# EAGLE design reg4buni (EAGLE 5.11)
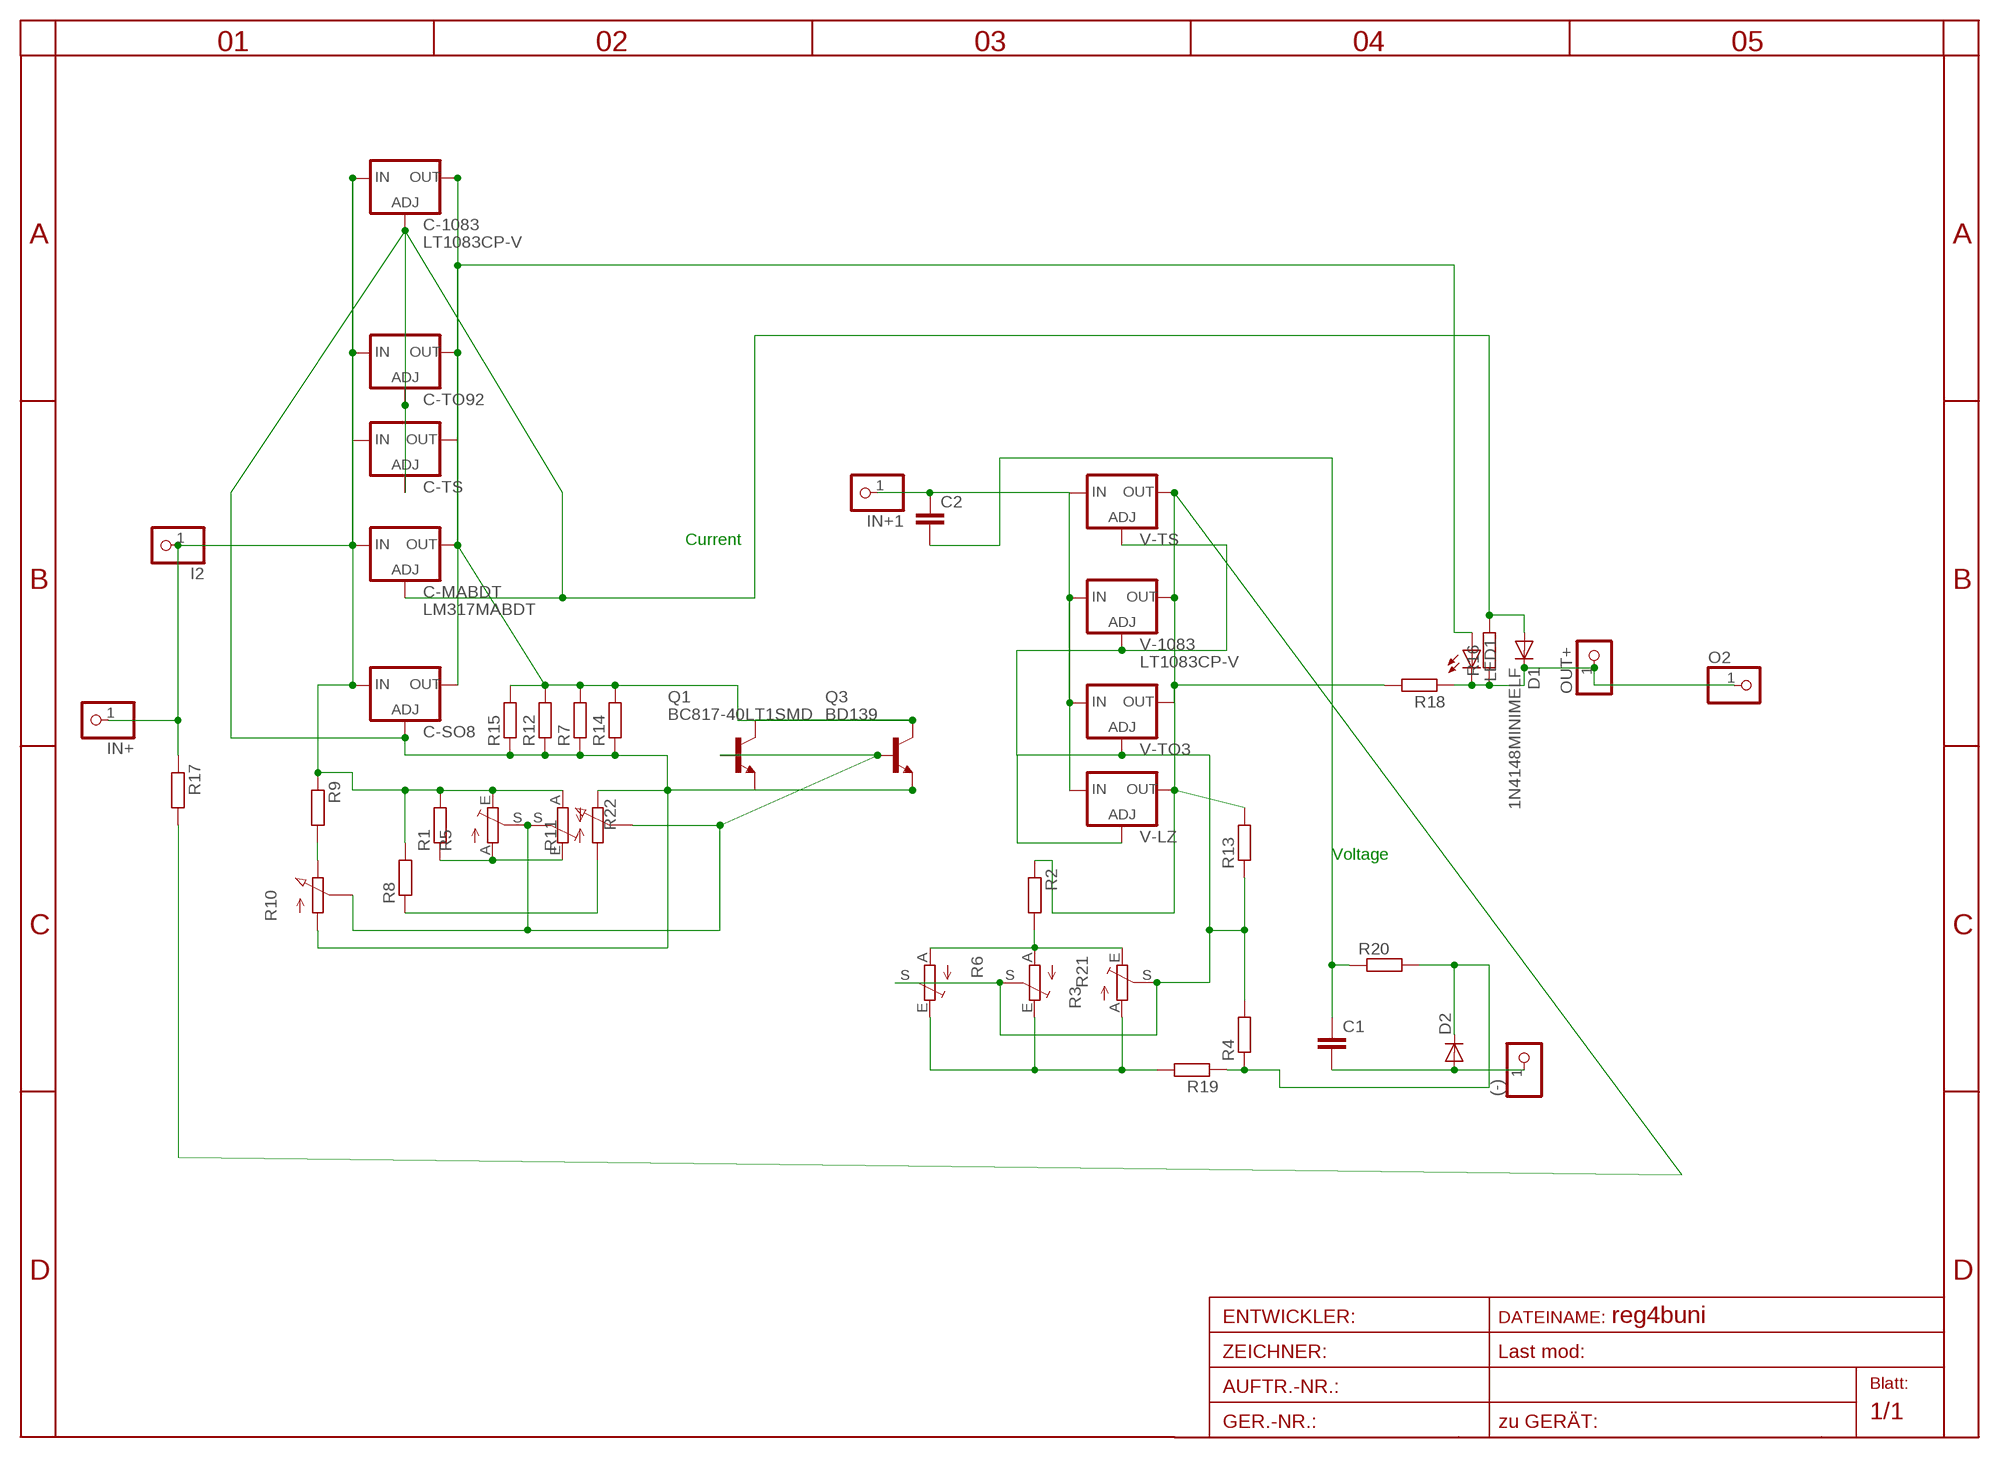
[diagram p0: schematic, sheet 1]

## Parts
(-)  PINHD-1X1  [1X01]
C1  C-EU050-025X075  [C050-025X075]
C2  C-EU050-025X075  [C050-025X075]
C-1083  LT1083CP-V  [TO247S]
C-MABDT  LM317MABDT  [DPACK]
C-SO8  LM317LM-OUTPIN7  [SO08]
C-TO92  LM317LZ  [317L]
C-TS  LM317TS  [317TS]
D1  1N4148MINIMELF  [MINIMELF]
D2  DIODE-MINIMELF  [MINIMELF]
I2  PINHD-1X11MM6  [1X1MM8]
IN+  PINHD-1X1  [1X01]
IN+1  PINHD-1X1  [1X01]
LED1  LEDCHIPLED_1206  [CHIPLED_1206]
O2  PINHD-1X11MM6  [1X1MM8]
OUT+  PINHD-1X1  [1X01]
Q1  BC817-40LT1SMD  [SOT23-BEC]
Q3  BD139  [TO126V]
R1  R-EU_0207/15  [0207/15]
R2  R-EU_0207/12  [0207/12]
R3  TRIM_EU-S64W  [S64W]
R4  R-EU_0204/7  [0204/7]
R5  TRIM_EU-S64W  [S64W]
R6  TRIM_EU-RAND160  [RANDL]
R7  R-EU_R1206  [R1206]
R8  R-EU_R1206  [R1206]
R9  R-EU_R1206  [R1206]
R10  PC25  [PC25]
R11  PC25  [PC25]
R12  R-EU_R1206  [R1206]
R13  R-EU_0204/5  [0204/5]
R14  R-EU_R1206  [R1206]
R15  R-EU_R1206  [R1206]
R16  R-EU_R0402  [R0402]
R17  R-EU_R0402  [R0402]
R18  R-EU_R0402  [R0402]
R19  R-EU_R0402  [R0402]
R20  R-EU_0207/12  [0207/12]
R21  TRIM_EU-EVND_H  [EVND8AA]
R22  TRIM_EU-RAND160  [RANDL]
V-1083  LT1083CP-V  [TO247S]
V-LZ  LM317LZ  [317L]
V-TO3  LM317-TO3  [TO3-K02]
V-TS  LM317TS  [317TS]

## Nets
ADJ2: R3.S R4.2 R6.S R13.1 R21.S V-1083.1(ADJ) V-LZ.1(ADJ) V-TO3.2(ADJ) V-TS.1(ADJ)
ADJUST: C-1083.1(ADJ) C-MABDT.1(ADJ) C-SO8.4(ADJ) C-TO92.1(ADJ) C-TS.1(ADJ) D1.A Q1.E Q3.3(E) R7.1 R10.A R11.E R12.1 R14.1 R15.1 R16.2
B1: Q1.B Q3.1(B) R5.S R10.S R11.S R22.S
IN+1: C2.1 IN+1.1 V-1083.3(IN) V-LZ.3(IN) V-TO3.1(IN) V-TS.3(IN)
IN-: (-).1 C1.2 D2.A
INPUT+: C-1083.3(IN) C-MABDT.3(IN) C-SO8.1(IN) C-TO92.3(IN) C-TS.3(IN) I2.1 IN+.1 R1.2 R5.E R8.2 R9.1 R17.1 R22.A
MINUS: R1.1 R5.A R22.E
N$1: R3.A R6.E R19.2 R21.E
N$2: R2.2 R3.E R6.A R21.A
N$5: R8.1 R11.A
N$6: R9.2 R10.E
N$7: C1.1 C2.2 R20.1
OUT1: C-1083.2(OUT) C-MABDT.4(OUT) C-SO8.7(OUT) C-TO92.2(OUT) C-TS.2(OUT) LED1.A Q1.C Q3.2(C) R7.2 R12.2 R14.2 R15.2
OUT2: R2.1 R13.2 R17.2 R18.2 V-1083.2(OUT) V-LZ.2(OUT) V-TO3.3(OUT) V-TS.2(OUT)
OUT+: D1.C LED1.C O2.1 OUT+.1 R16.1 R18.1
VIRT-: D2.C R4.1 R19.1 R20.2

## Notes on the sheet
- Current
- Voltage

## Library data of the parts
(-) IN+ IN+1 OUT+ = pinhead(2):PINHD-1X1: PIN HEADER
C1 C2 = rcl:C-EU: CAPACITOR, European symbol
C-1083 V-1083 = linear-technology-2:LT1083*: 7.5A Low Dropout Positive Adjustable Regulators
C-MABDT = v-reg:LM317?*: 500 mA Adjustable Output Positive Voltage Regulator Source: http://www.onsemi.co.jp .. LM317M-D.PDF
C-SO8 C-TO92 V-LZ = v-reg-3:LM317L: Adjustable Voltage Regulator, 1.2V to 37V, 100mA
C-TS V-TS = v-reg:LM317TS: VOLTAGE REGULATOR
D1 = diode-1:1N4148: DIODE
D2 = diode:DIODE-: DIODE
I2 O2 = pinhead:PINHD-1X1: PIN HEADER
LED1 = led:LED: LED
Q1 = transistor-npn:BC817*: NPN Transistor
Q3 = transistor-npn:BD139*: NPN Transistor
R1 R2 R4 R7-R9 R12-R20 = rcl-2:R-EU_: RESISTOR, European symbol
R3 R5 R6 R21 R22 = pot:TRIM_EU-: POTENTIOMETER
R10 R11 = pot-vitrohm:PC25: VITROHM POTENTIOMETER
V-TO3 = v-reg:LM317-TO3: VOLTAGE REGULATOR

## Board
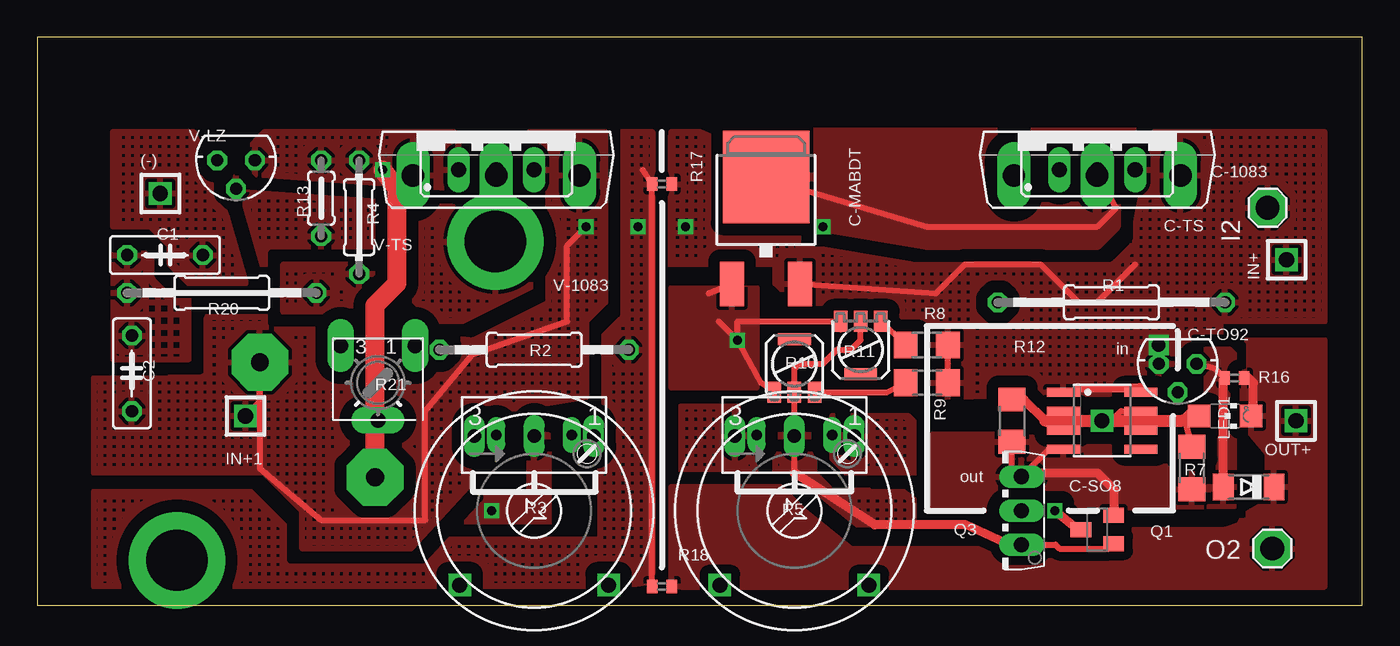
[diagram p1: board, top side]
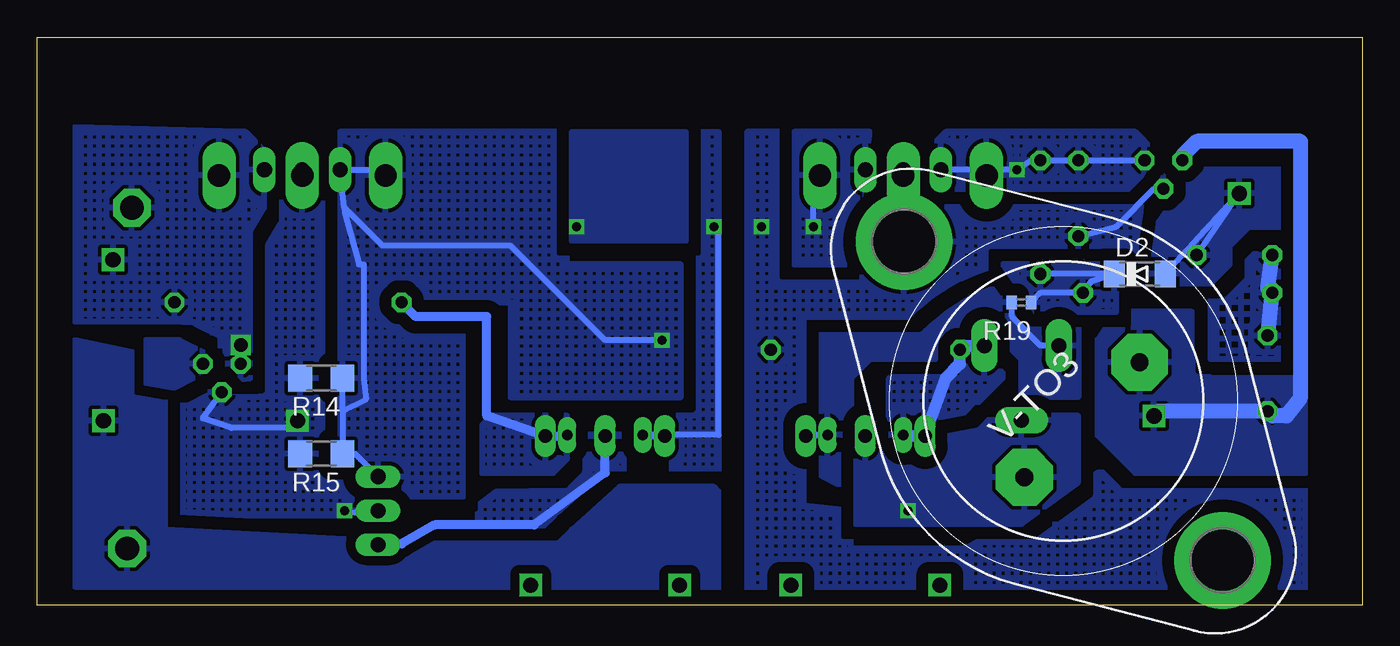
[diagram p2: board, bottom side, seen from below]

Size 88.9 x 38.1 mm. Coordinates in mm from the lower left corner, seen from the top.
Outline: 0,0 88.9,0 88.9,38.1 0,38.1 0,0
Copper layers (1*16): Top 0.035mm / dielectric 1.5mm / Bottom 0.035mm
Design rules "default": minimum track width 10mil, minimum drill 24mil, track to track 8mil, track to pad 8mil, pad to pad 8mil, via to via 8mil, smd to smd 8mil, copper to edge 40mil, drill to drill 8mil, minimum pad ring 10mil, minimum via ring 8mil, stop-mask expansion 4mil, vias tented up to drill 0mil, thermal gap 10mil

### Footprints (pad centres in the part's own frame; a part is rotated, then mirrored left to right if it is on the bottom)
1X01 = drill 1.016 square: 1 0,0
C050-025X075 = drill 0.813 octagon: 1 -2.54,0; 2 2.54,0
TO247S = drill 1.499 long: 1 -5.588,-2.921; 2 0,-2.921; 3 5.588,-2.921
DPACK = smd 1.6 x 3: 1 -2.28,-4.8; 3 2.28,-4.8 | smd 5.8 x 6.2: 4 0,2.38
SO08 = smd 0.6 x 2.2: 1 -1.905,-2.6; 2 -0.635,-2.6; 3 0.635,-2.6; 4 1.905,-2.6; 5 1.905,2.6; 6 0.635,2.6; 7 -0.635,2.6; 8 -1.905,2.6
317L = drill 0.813 octagon: 1 -1.27,0; 2 0,1.905; 3 1.27,0
317TS = drill 1.016 long: 1 -2.54,-2.54; 2 0,-2.54; 3 2.54,-2.54
MINIMELF = smd 1.4 x 1.8: A 1.7,0; C -1.7,0
1X1MM8 = drill 1.6 pad 2.54 octagon: 1 0,0
CHIPLED_1206 = smd 1.5 x 1.5: A 0,-1.75; C 0,1.75
SOT23-BEC = smd 1 x 1.4: B -0.95,-1.1; C 0,1.1; E 0.95,-1.1
TO126V = drill 1.016 long: 1 -2.286,-1.27; 2 0,-1.27; 3 2.286,-1.27
0207/15 = drill 0.813 octagon: 1 -7.62,0; 2 7.62,0
0207/12 = drill 0.813 octagon: 1 -6.35,0; 2 6.35,0
S64W = drill 0.7 long: A 2.54,1.27; E -2.54,1.27; S 0,1.27
0204/7 = drill 0.813 octagon: 1 -3.81,0; 2 3.81,0
RANDL = drill 0.9 long: A -4,5; E 4,5; S 0,5 | drill 1 square: P$1 -5,-5; P$2 5,-5
R1206 = smd 1.6 x 1.803: 1 -1.422,0; 2 1.422,0
PC25 = smd 2.2 x 0.8: 4 0,1.65 | smd 0.9 x 1.4: A -1.35,-1.9; E 1.35,-1.9; S 0,-1.9
0204/5 = drill 0.813 octagon: 1 -2.54,0; 2 2.54,0
R0402 = smd 0.7 x 0.9: 1 -0.65,0; 2 0.65,0
EVND8AA = drill 1 pad 1.778 long: A -2.5,-2.5; E 2.5,-2.5; S 0,2.5
TO3-K02 = drill 1.194 pad 3.81 octagon: 1 -1.778,-5.461; 2 -1.778,5.461 | drill 4.115 pad 6.477 round: 3 15.113,0; 3@ -15.113,0

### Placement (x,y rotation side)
(-)  8.26,27.62 0 top
C1  8.57,23.5 0 top
C2  6.35,15.56 90 top
C-1083  71.12,31.75 0 top
C-MABDT  48.9,26.35 0 top
C-SO8  71.44,12.38 270 top
C-TO92  76.52,16.19 180 top
C-TS  71.12,31.75 0 top
D1  81.28,7.94 180 top
D2  14.92,22.23 0 bottom
I2  82.55,26.67 0 top
IN+  83.82,23.18 0 top
IN+1  13.97,12.7 0 top
LED1  79.69,12.7 270 top
O2  82.87,3.81 0 top
OUT+  84.45,12.38 90 top
Q1  71.12,5.08 90 top
Q3  64.77,6.35 90 top
R1  72.07,20.32 0 top
R2  33.34,17.14 180 top
R3  33.34,10.16 0 top
R4  21.59,26.04 90 top
R5  50.8,10.16 0 top
R6  33.34,6.35 0 top
R7  77.47,9.21 90 top
R8  59.69,17.46 0 top
R9  59.69,14.92 180 top
R10  50.8,16.19 0 top
R11  55.24,17.14 180 top
R12  65.41,12.38 90 top
R13  19.05,27.3 270 top
R14  69.85,15.24 180 bottom
R15  69.85,10.16 180 bottom
R16  80.33,15.24 180 top
R17  41.91,28.26 180 top
R18  41.91,1.27 180 top
R19  22.86,20.32 180 bottom
R20  12.38,20.95 0 top
R21  22.86,14.92 180 top
R22  50.8,6.35 0 top
V-1083  30.8,31.75 0 top
V-LZ  13.34,29.84 180 top
V-TO3  20.06,13.71 135 bottom
V-TS  30.8,31.75 0 top

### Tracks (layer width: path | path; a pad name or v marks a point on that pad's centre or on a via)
ADJ2  (via drill 0.6)
  Top 1.27: V-TO3.2 22.66,20.12 24.13,21.59 24.13,27.94 v23.18,29.21
  Bottom 0.406: V-LZ.1 R13.1 R4.2 22.23,29.84 v23.18,29.21 24.13,29.21 24.86,28.48 | 24.86,28.48 V-1083.1 25.59,29.21 V-TS.1 | 24.86,28.48 24.32,27.94
  other vias: 30.48,6.35
  pour Bottom (isolate 0.813, hatched): 13.97,30.48 15.24,31.75 27.94,31.75 29.21,30.48 29.21,29.21 27.94,27.94 15.24,27.94
  pour Bottom (isolate 0.813, rank 2): 19.05,12.7 24.77,12.7 25.72,11.75 33.97,10.16 33.97,5.46 22.86,5.46 19.05,8.26
  pour Top (isolate 0.813, hatched): 13.97,30.48 15.24,31.75 27.94,31.75 29.21,30.48 29.21,29.21 27.94,27.94 14.61,28.89
  pour Top (isolate 0.813, rank 5): 34.29,11.43 34.29,5.08 27.94,5.08 27.94,6.35 29.21,7.62 33.02,7.62 33.02,11.43
ADJUST  (via drill 0.6)
  Top 0.406: C-SO8.4 67.88,10.48 Q3.3 | Q3.3 65.98,8.57 | R12.1 65.41,9.27 Q3.3 | 45.05,20.92 C-MABDT.1 | C-TO92.1 79.06,15.86 R16.2 | R10.A 48.57,14.93 v46.99,17.78 | R11.E 53.9,18.5 53.34,19.05 46.99,19.05 v46.99,17.78 | v46.99,17.78 45.72,19.05
  Top 0.61: D1.A 79.58,15.14 R16.2 | Q1.E 72.22,7.79 71.12,8.89 66.29,8.89 Q3.3
  Bottom 0.406: R15.1 68.58,10.01 | 68.3,26.7 68.26,26.35 67.31,22.86 66.99,22.86 66.99,15.24 66.84,13.8 68.43,13.02 | 68.3,26.7 C-TS.1 65.91,29.21 C-1083.1 | 68.43,13.02 R15.1 | 68.43,13.02 R14.1 | v46.99,17.78 50.8,17.78 57.15,24.13 65.73,24.13 68.3,26.7 | R15.1 67.56,10.16 Q3.3
  pour Top (isolate 0.813): 42.55,21.27 48.26,21.27 48.26,14.61 42.55,14.61
  pour Top (isolate 0.813): 60.01,11.43 60.01,6.35 80.33,6.67 80.33,16.83 80.01,17.14 78.42,17.14 78.42,9.84 74.93,10.16 72.39,10.16 71.12,11.43
  pour Bottom (isolate 0.61): 77.47,16.19 77.47,16.83 79.38,17.78 81.6,17.78 81.6,14.92 79.69,14.61 78.42,15.24
  pour Bottom (isolate 0.813, rank 3, hatched): 53.34,31.75 68.58,31.75 68.58,10.16 64.77,7.3 60.33,7.3 60.33,20.32 57.15,20.32 57.15,13.97 45.72,13.97 45.72,22.86 53.34,22.86
B1
  Top 0.406: Q1.B 71.9,3.81 68.58,3.81 68.33,4.06 Q3.1 65.79,3.81 | R5.S R10.S 50.8,15.88 51.12,16.19 52.7,16.19 53.66,17.14 54.61,17.14 55.24,17.78 R11.S | 50.8,8.89 R22.S
  Top 0.61: 65.79,3.81 62.29,5.4 56.2,5.4 50.8,8.89
  Bottom 0.406: 64.45,4.13 Q3.1
  Bottom 0.61: 64.45,4.13 62.23,5.4 55.56,5.4 50.8,8.89 R5.S
  pour Bottom (isolate 0.813, rank 6, hatched): 49.53,11.43 52.07,11.43 55.88,7.62 58.1,7.62 59.37,6.67 59.37,5.4 54.61,5.08 52.39,6.67 50.8,6.99 49.53,8.26
  pour Top (isolate 0.813, rank 6, hatched): 49.53,11.43 52.07,11.43 55.88,7.62 58.1,7.62 59.37,6.67 59.37,5.4 53.66,5.4 50.8,6.99 49.53,8.26
IN+1  (via drill 0.6)
  Top 0.406: v36.83,25.4 35.56,24.13 35.56,19.05 29.21,16.83 26.04,13.02 26.04,5.71 19.05,5.71 14.94,9.19 V-TO3.1 14.94,13.67 IN+1.1
  Bottom 0.406: 13.65,13.02 IN+1.1 | 6.03,12.7 C2.1 | v36.83,25.4 36.83,28.38 V-1083.3
  Bottom 1.016: C2.1 13.65,13.02 | V-LZ.3 12.06,30.16 11.11,31.11 4.13,31.11 4.13,13.97 5.08,12.7 6.03,12.7
  pour Bottom (isolate 0.813, hatched): 33.02,31.75 38.1,31.75 38.1,22.86 34.29,22.86
  pour Top (isolate 0.813, rank 3, hatched): 3.81,15.24 8.89,15.24 11.43,19.37 17.78,19.37 29.21,17.78 34.29,20.32 34.29,30.48 33.02,31.75 38.1,31.75 38.1,20.32 36.83,19.05 36.83,13.97 29.21,12.7 28.89,7.94 25.08,3.81 17.78,3.81 17.78,6.35 15.24,8.89 3.81,8.89
  pour Bottom (isolate 0.813, rank 3): 17.78,17.78 17.78,11.43 15.24,8.89 3.81,8.89 3.81,15.24 10.16,15.24 11.43,16.51 11.43,19.68 16.51,19.68
IN-
  Bottom 0.406: C1.2 (-).1 D2.A
  pour Bottom (isolate 0.813): 5.08,29.21 11.43,29.21 12.38,27.62 13.65,25.72 14.29,21.59 10.16,21.59 8.89,22.86 8.89,24.13 7.62,25.4 5.08,25.4
  pour Top (isolate 0.813, hatched): 5.08,31.75 10.48,31.75 12.7,26.04 13.97,21.59 10.16,21.59 8.89,22.86 8.89,24.13 7.62,25.4 5.08,25.4
INPUT+  (via drill 0.6, 0.9)
  Top 0.406: R9.1 R8.2 | C-SO8.1 69.53,14.29 69.85,14.61 | C-MABDT.3 60.29,20.92 62.23,22.86 67.31,22.86 69.85,20.32 71.12,20.32 73.66,22.86
  Top 0.61: 69.85,14.61 73.98,14.61
  Bottom 0.406: R22.A 48.26,11.35 R5.E 43.18,11.43 43.18,25.08 v43.5,25.4
  other vias: 75.25,17.46
  pour Top (isolate 0.813, rank 5, hatched): 74.93,31.75 86.36,31.75 86.36,19.05 79.38,19.05 79.38,14.29 60.96,13.97 57.15,13.97 49.53,21.59 49.53,22.86 41.91,22.86 42.55,31.75 44.45,31.75 62.23,24.13 73.66,24.13 73.66,25.4
  pour Bottom (isolate 0.813, rank 2, hatched): 75.25,31.75 86.36,32.07 86.36,19.05 79.06,19.05 79.06,17.78 77.47,14.92 74.61,15.24 74.61,25.08 73.66,26.67 73.66,30.48 74.93,31.75
  pour Bottom (isolate 0.813, rank 5, hatched): 43.18,31.75 43.18,8.89 46.35,8.89 45.09,31.75
  pour Top (isolate 0.813, rank 5, hatched): 43.18,13.34 43.18,8.89 48.26,8.89 46.99,13.34
MINUS
  Bottom 0.406: 53.42,11.35 R5.A
  Bottom 0.61: R1.1 63.5,19.37 58.74,19.37 58.74,12.7 R22.E 53.42,11.35
  pour Bottom (isolate 0.813, rank 4, hatched): 53.34,12.7 58.42,12.7 59.05,12.06 59.05,8.89 54.29,8.89 53.34,9.84
  pour Top (isolate 0.813, rank 4, hatched): 53.34,12.7 58.42,12.7 59.05,12.06 59.05,8.89 54.29,8.89 53.34,9.84
N$1
  Bottom 0.406: R21.E 21.59,17.42 23.5,19.37 R19.2 | R3.A 37.34,11.43 R6.E
  pour Bottom (isolate 0.813, rank 5): 39.69,10.48 37.15,18.1 35.56,19.05 29.21,19.05 26.67,21.59 21.59,21.59 19.05,19.05 19.05,13.97 22.86,13.97 22.86,16.51 24.13,17.78 26.67,17.78 27.94,16.51 33.02,16.51 34.29,15.24 34.29,7.62
N$2
  Bottom 0.813: R21.A 26.71,17.42 R2.2 26.99,16.19 27.94,15.24 29.21,11.75 R6.A 30.72,11.35 R3.E
  pour Bottom (isolate 0.813, rank 6, hatched): 24.13,17.78 24.13,15.24 29.21,10.16 31.75,10.16 31.75,15.24
N$5
  Top 0.406: R11.A 57.64,18.09 R8.1
N$6
  Top 0.406: 57.78,14.92 R9.2 57,14.29 53.41,14.29 R10.E
N$7
  Bottom 0.406: R20.1 6.35,21.27
  Bottom 1.016: C2.2 R20.1 | 6.35,21.27 C1.1
  pour Bottom (isolate 0.813, rank 2, hatched): 5.08,24.13 5.08,16.51 10.16,16.51 10.16,22.86
  pour Top (isolate 0.813, rank 2, hatched): 5.08,24.13 5.08,16.51 10.16,16.51 10.16,22.86
OUT1  (via drill 0.6, 1)
  Top 0.406: C-MABDT.4 50.64,28.1 59.69,25.4 71.12,25.4 72.39,26.67 C-1083.2 | 69.85,5.08 Q1.C | v71.44,12.38 72.39,12.7 72.71,13.02 C-SO8.7 | R7.2 77,12.38 76.83,12.38 | R12.2 66.21,13.8 | 77.47,13.02 LED1.A
  Top 0.61: v68.26,6.35 69.85,5.08 | 66.21,13.8 67.63,12.38 | 76.83,12.38 77.47,13.02
  Top 0.813: 76.83,12.38 v71.44,12.38 67.63,12.38
  Bottom 0.406: v68.26,6.35 66.36,6.03 | C-TO92.2 77.79,12.53 75.88,11.9 71.92,11.9 v71.44,12.38
  other vias: 52.7,25.4
  pour Bottom (isolate 0.813, rank 5, hatched): 69.85,28.89 73.34,29.53 74.3,22.23 74.3,14.29 78.11,14.29 79.38,13.65 79.69,6.03 66.67,6.03
  pour Top (isolate 0.813, rank 3): 52.07,31.75 73.66,31.75 72.39,29.21 72.39,25.4 71.12,24.13 59.69,24.13 52.07,25.4
  pour Bottom (isolate 0.813, rank 2): 45.4,31.75 45.4,24.45 53.02,24.45 53.02,31.75
OUT2  (via drill 0.6)
  Top 0.406: 40.64,29.21 R17.2 R18.2
  Bottom 0.406: V-LZ.2 13.97,27.94 16.51,25.4 R13.2 | v40.32,25.4 40.64,25.4 | V-TO3.3 30.74,28.77 V-1083.2 V-TS.2
  pour Bottom (isolate 0.813, rank 4, hatched): 12.7,29.21 15.24,29.21 16.51,27.94 31.75,27.94 34.29,25.4 34.29,24.13 35.56,22.86 38.1,22.86 38.1,31.75 41.27,31.75 41.27,0.32 3.81,0 3.81,8.89 17.78,8.89 26.67,3.81 34.29,3.81 34.29,6.35 37.47,6.67 37.47,19.37 30.48,19.37 arc38 22.86,23.18 13.97,22.86 12.7,24.13
  pour Top (isolate 0.813, rank 4, hatched): 12.7,29.21 15.24,29.21 16.51,27.94 31.75,27.94 34.29,25.4 34.29,24.13 35.56,22.86 38.1,22.86 38.1,31.75 41.27,31.75 41.27,1.59 39.37,1.27 3.81,1.27 3.81,7.62 16.51,7.62 17.14,4.45 37.78,4.45 37.78,20.32 36.83,20.32 35.56,19.05 26.67,19.05 22.86,22.86 13.97,22.86 12.7,24.13
OUT+
  Top 0.61: R16.1 81.28,15.24 81.6,14.92 81.6,12.86 LED1.C
  pour Top (isolate 0.61, rank 2): 80.96,17.78 86.36,17.78 86.36,1.27 85.72,0.64 43.18,0.64 42.55,1.27 42.55,7.94 49.85,7.94 51.44,6.35 54.61,3.81 71.12,3.81 71.12,5.08 79.69,5.08 80.64,5.4 80.96,6.03 82.55,6.99 82.55,10.16 80.96,12.06 80.96,13.34 80.64,13.65 80.64,17.46
  pour Bottom (isolate 0.61, rank 2): 80.33,16.51 86.36,17.78 86.36,1.27 85.72,0.64 43.18,0.64 43.18,7.62 43.5,7.94 49.85,7.94 53.02,5.08 53.98,4.13 61.28,4.13 68.26,4.45 80.33,5.08
VIRT-
  Bottom 0.406: R19.1 21.61,20.95 R20.2 18.21,21.7 D2.C R4.1
  pour Bottom (isolate 0.813, hatched): 16.51,22.86 24.13,22.86 21.91,19.68 16.51,19.68
  pour Top (isolate 0.813, hatched): 16.51,22.86 22.86,22.86 22.86,19.68 16.51,19.68

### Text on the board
tNames: in | out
